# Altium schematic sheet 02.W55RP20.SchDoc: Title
size A4; Team: Team Platform; Date: *******; ApprovedBy: *******; CheckedBy: None; Author: *******; CompanyName: *******; DrawnBy: Jaden; Engineer: *******; Organization: *******; Address1: *******; Address2: *******; Address3: *******; Address4: *******; DocumentNumber: 2; Revision: *******; SheetNumber: 2; SheetTotal: 6
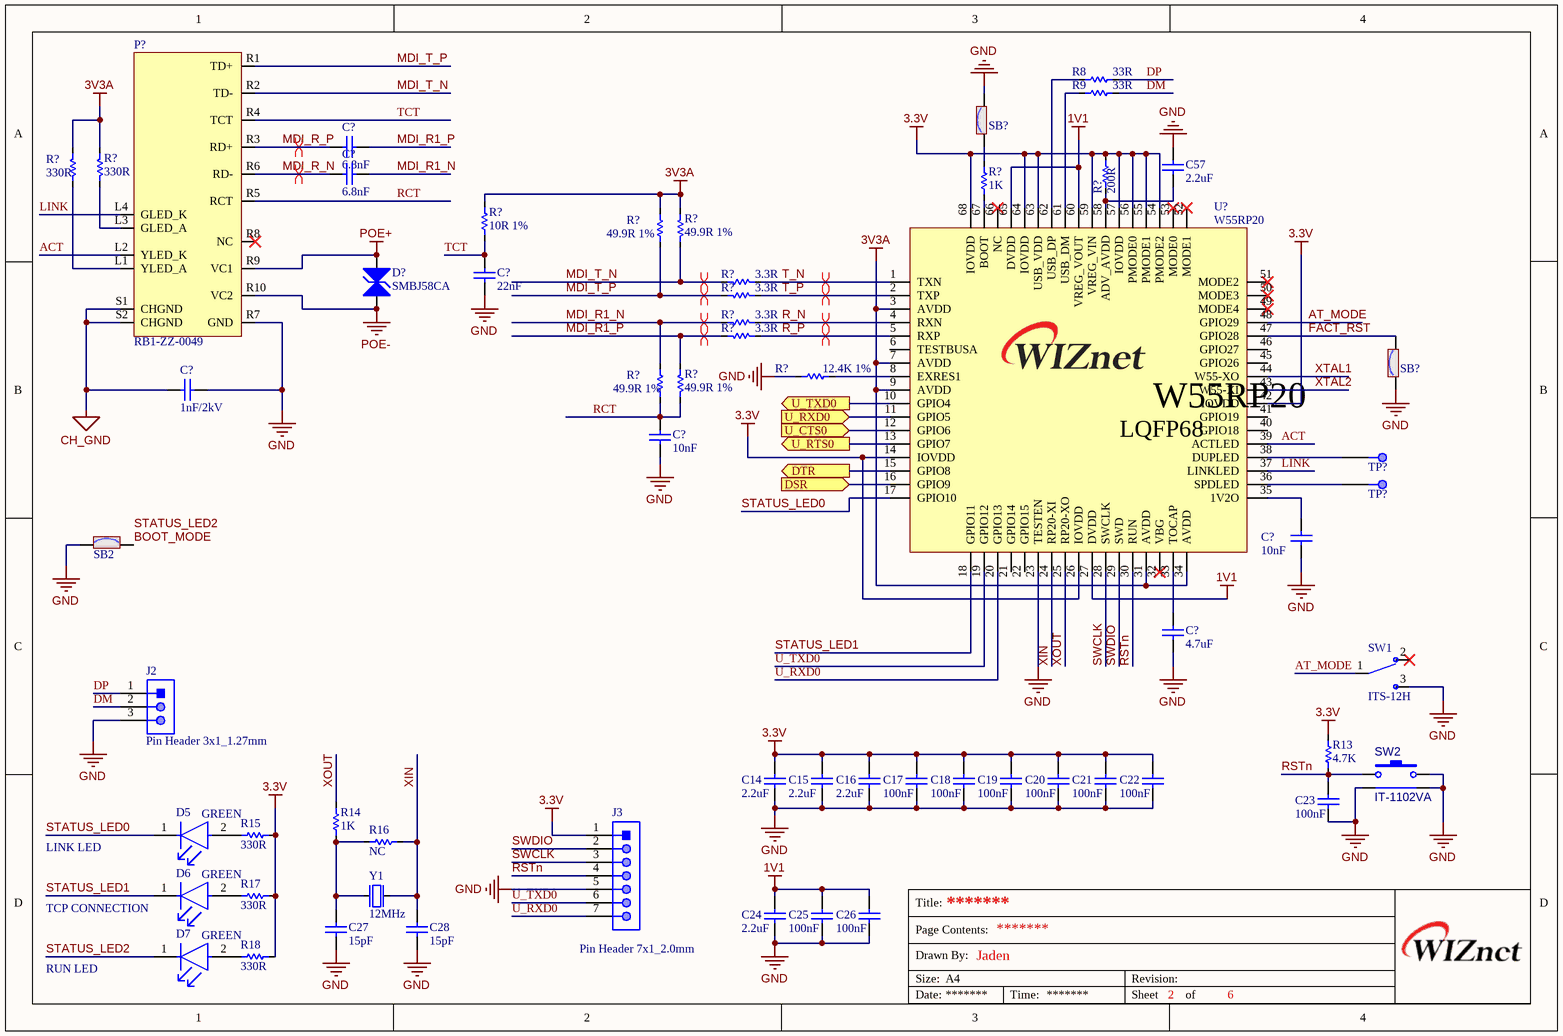
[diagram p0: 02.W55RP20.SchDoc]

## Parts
(Parts that share a designator on the sheet are numbered #1, #2 ... from top to bottom, then left to right.)
C14  2.2uF  [CAP-0402]
C15  2.2uF  [CAP-0402]
C16  2.2uF  [CAP-0402]
C17  100nF  [CAP-0402]
C18  100nF  [CAP-0402]
C19  100nF  [CAP-0402]
C20  100nF  [CAP-0402]
C21  100nF  [CAP-0402]
C22  100nF  [CAP-0402]
C23  100nF  [CAP-0402]
C24  2.2uF  [CAP-0402]
C25  100nF  [CAP-0402]
C26  100nF  [CAP-0402]
C27  15pF  [CAP-0402]
C28  15pF  [CAP-0402]
C57  2.2uF  [CAP-0402]
C?#1  6.8nF  [CAP-0402]
C?#2  6.8nF  [CAP-0402]
C?#3  22nF  [CAP-0402]
C?#4  1nF/2kV  [CAP-1808]
C?#5  10nF  [CAP-0402]
C?#6  10nF  [CAP-0402]
C?#7  4.7uF  [CAP-0603-3]
D5  GREEN  [KLH-117]
D6  GREEN  [KLH-117]
D7  GREEN  [KLH-117]
D?  SMBJ58CA  [DO-214AA/SMB(TVS)]
J2  Pin Header 3x1_1.27mm  [PIN-HEADER(DIP)_3X1_1.27MM]
J3  Pin Header 7x1_2.0mm  [Pin-Header(DIP)_7x1_2.0mm]
P?  RB1-ZZ-0049  [RB1-ZZ-0049]
R8  33R  [RES-0402]
R9  33R  [RES-0402]
R13  4.7K  [RES-0402]
R14  1K  [RES-0402]
R15  330R  [RES-0402]
R16  NC  [RES-0402]
R17  330R  [RES-0402]
R18  330R  [RES-0402]
R?#1  330R  [RES-0402]
R?#2  330R  [RES-0402]
R?#3  200R  [RES-0402]
R?#4  1K  [RES-0402]
R?#5  10R 1%  [RES-0402]
R?#6  49.9R 1%  [RES-0402]
R?#7  49.9R 1%  [RES-0402]
R?#8  3.3R  [RES-0402]
R?#9  3.3R  [RES-0402]
R?#10  3.3R  [RES-0402]
R?#11  3.3R  [RES-0402]
R?#12  12.4K 1%  [RES-0402]
R?#13  49.9R 1%  [RES-0402]
R?#14  49.9R 1%  [RES-0402]
SB2  SB_ON  [SOLDER-BRIDGE_R0402-0R]  (value not drawn)
SB?#1  SB_ON  [SOLDER-BRIDGE_R0402-0R]  (value not drawn)
SB?#2  SB_ON  [SOLDER-BRIDGE_R0402-0R]  (value not drawn)
SW1  ITS-12H  [ITS-12H]
SW2  IT-1102VA  [IT-1102VA]
TP?#1  TPS  [TPS]  (value not drawn)  (no BOM)
TP?#2  TPS  [TPS]  (value not drawn)  (no BOM)
U?  W55RP20  [QFN68(0.4/8X8)]
Y1  12MHz  [OSC-TZ1067B]

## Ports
DSR (in), DTR (out), U_CTS0 (in), U_RTS0 (out), U_RXD0 (in), U_TXD0 (out)

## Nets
1V1: C24.2 C25.2 C26.2 U?.27(DVDD) U?.60(VREG_VOUT) U?.65(DVDD)
3.3V: C14.2 C15.2 C16.2 C17.2 C18.2 C19.2 C20.2 C21.2 C22.2 J3.1 R13.2 R15.2 R17.2 R18.2 R?#3.2 U?.14(IOVDD) U?.26(IOVDD) U?.42(IOVDD) U?.54(PMODE2) U?.55(PMODE1) U?.56(PMODE0) U?.57(IOVDD) U?.59(VREG_VIN) U?.63(USB_VDD) U?.64(IOVDD) U?.68(IOVDD)
3V3A: R?#1.2 R?#2.2 R?#5.2 R?#6.2 R?#7.2 U?.3(AVDD) U?.7(AVDD) U?.9(AVDD) U?.31(AVDD) U?.34(AVDD)
CH_GND: C?#4.1 P?.S1(CHGND) P?.S2(CHGND)
GND: C14.1 C15.1 C16.1 C17.1 C18.1 C19.1 C20.1 C21.1 C22.1 C23.1 C24.1 C25.1 C26.1 C27.1 C28.1 C57.1 C?#3.1 C?#4.2 C?#5.1 C?#6.1 C?#7.1 J2.3 J3.5 P?.R7(GND) R?#12.1 SB2.1 SB?#1.2 SB?#2.1 SW1.3 SW2.2 SW2.3 SW2.4 U?.23(TESTEN) Y1.2 Y1.4
POE+: D?.2(A2) P?.R9(VC1)
POE-: D?.1(A1) P?.R10(VC2)
ACT: P?.L2(YLED_K) U?.39(ACTLED)
AT_MODE: SW1.1 U?.48(GPIO29)
BOOT_MODE: SB2.2
DM: J2.2 R9.1
DP: J2.1 R8.1
DSR: U?.16(GPIO9) ; port DSR
DTR: U?.15(GPIO8) ; port DTR
FACT_RST: SB?#2.2 U?.47(GPIO28)
LINK: P?.L4(GLED_K) U?.37(LINKLED)
MDI_R1_N: C?#2.1 R?#10.2 R?#13.2
MDI_R1_P: C?#1.1 R?#11.2 R?#14.2
MDI_R_N: C?#2.2 P?.R6(RD-)
MDI_R_P: C?#1.2 P?.R3(RD+)
MDI_T_N: P?.R2(TD-) R?#7.1 R?#8.2
MDI_T_P: P?.R1(TD+) R?#6.1 R?#9.2
R_N: R?#10.1 U?.4(RXN)
R_P: R?#11.1 U?.5(RXP)
RCT: C?#5.2 P?.R5(RCT) R?#13.1 R?#14.1
RSTn: C23.2 J3.4 R13.1 SW2.1 U?.30(RUN)
STATUS_LED0: D5.1(C) U?.17(GPIO10)
STATUS_LED1: D6.1(C) U?.18(GPIO11)
STATUS_LED2: D7.1(C)
SWCLK: J3.3 U?.28(SWCLK)
SWDIO: J3.2 U?.29(SWD)
T_N: R?#8.1 U?.1(TXN)
T_P: R?#9.1 U?.2(TXP)
TCT: C?#3.2 P?.R4(TCT) R?#5.1
U_CTS0: U?.12(GPIO6) ; port U_CTS0
U_RTS0: U?.13(GPIO7) ; port U_RTS0
U_RXD0: J3.7 U?.20(GPIO13)
U_RXD0: U?.11(GPIO5) ; port U_RXD0  [a separate net that carries the same name]
U_TXD0: J3.6 U?.19(GPIO12)
U_TXD0: U?.10(GPIO4) ; port U_TXD0  [a separate net that carries the same name]
XIN: C28.2 R16.2 U?.24(RP20-XI) Y1.3(out)
XOUT: R14.2 U?.25(RP20-XO)
XTAL1: U?.44(W55-XO)
XTAL2: U?.43(W55-XI)
NetC27_2: C27.2 R14.1 R16.1 Y1.1(inp)
NetC57_2: C57.2 R?#3.1 U?.58(ADV_AVDD)
NetC?#6_2: C?#6.2 U?.35(1V2O)
NetC?#7_2: C?#7.2 U?.33(TOCAP)
NetD5_2: D5.2(A) R15.1
NetD6_2: D6.2(A) R17.1
NetD7_2: D7.2(A) R18.1
NetP?_L1: P?.L1(YLED_A) R?#1.1
NetP?_L3: P?.L3(GLED_A) R?#2.1
NetR8_2: R8.2 U?.62(USB_DP)
NetR9_2: R9.2 U?.61(USB_DM)
NetR?#4_1: R?#4.1 U?.67(BOOT)
NetR?#4_2: R?#4.2 SB?#1.1
NetR?#12_2: R?#12.2 U?.8(EXRES1)
NetTP?#1_1: TP?#1.1 U?.38(DUPLED)
NetTP?#2_1: TP?#2.1 U?.36(SPDLED)

Not connected (* = marked no-connect by the designer): P? R8(NC)*; SW1 2*; U? 6(TESTBUSA) 21(GPIO14) 22(GPIO15) 32(VBG)* 40(GPIO18) 41(GPIO19) 45(GPIO26) 46(GPIO27) 49(MODE4)* 50(MODE3)* 51(MODE2)* 52(MODE1)* 53(MODE0)* 66(NC)*

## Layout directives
differential pair: MDI_R1_N, MDI_R1_P, MDI_R_N, MDI_R_P, MDI_T_N, MDI_T_P, R_N, R_P, T_N, T_P

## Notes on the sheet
- LINK LED
- TCP CONNECTION
- RUN LED
- Labels drawn without touching a wire or pin: STATUS_LED2

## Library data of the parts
C14-C28 C57 C?#1-C?#3 C?#5 C?#6 = CAP-0402: MLCC-0402(1005)
C?#4 = CAP-1808: MLCC-1808(4520)
C?#7 = CAP-0603: MLCC-0603(1608)
D5-D7 = KLH-117: LED 3MM HIGH EFF GREEN; Manufacturer: Dialight; Manufacturer Part Number: 551-0207F; Viewing Angle: 45°; Lens Size: 5mm; Dominant Wavelength: 563nm; Test Current: 10mA; Power Dissipation: 75mW; Luminous Intensity: 16mcd; Operating Supply Voltage: 2.1V; Reverse Voltage: 3V; Number of LEDs: 1; Lens Style: Diffused; Element Configuration: Single
D? = DIODE-TVS (SMB): PartNumber: SMAJ58CA-E3/61; Manufacturer: Vishay Semiconductor; Manufacturer: Vishay Semiconductors; PPPM (W): 400, 300; ID (uA): 2; IFSM: 40 A; VWM (V): 58; VBR Bi-Directional (V): 6.4 to 231; Packing: Tape and Reel
J2 = Pin Header 3x1_1.27mm: Connector; Manufacturer_Name: Harwin; Manufacturer_Part_Number: M22-2010705
J3 = Pin Header 7x1_2.0mm: Connector; Manufacturer_Name: Harwin; Manufacturer_Part_Number: M22-2010705
P? = RB1-ZZ-0049: PoE RJ45
R8 R9 R13-R18 R?#1-R?#14 = RES-0402: Chip Resistor 0402(1005)
SB2 SB?#1 SB?#2 = Soldering Jumper: Solder Bridge 0402 ON; Internal_Part_Number: MCD-01618; Part_Type: Mechanical; Manufacturer_Part_Number: RC0402JR-070RL; Manufacturer: YAGEO; Provided_By: SUBCO
SW1 = ITS-12H: Slide Switch
SW2 = IT-1102VA: IT-1102VA-3.85MM
TP?#1 TP?#2 = TPS: Test_point; Manufacturer: Wurth Elektronik; Part Number: 61300211121; Rated Current: 3A; Gender: Male; Withstanding Voltage: 500VAC; Working Voltage: 250VAC; Pitch: 2.54mm; Contact Resistance: 20mOhm; Row Number: Single; Pin Number: 2
U? = W55RP20: WIZnet Hardwired TCP/IP Chip
Y1 = OSC-TZ1067B-12MHz: X-tal 12MHz,3.2x2.5 SMD, CL=20pF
